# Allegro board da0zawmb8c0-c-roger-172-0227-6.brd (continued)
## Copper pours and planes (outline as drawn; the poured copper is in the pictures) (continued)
VCCDSW_GPIO on TOP (solid shape): 85.28,31.61 85.28,31.23 84.77,31.23 84.52,30.97 84.01,30.97 83.88,31.1 83.88,31.74 84.14,31.99 84.14,32.37 84.52,32.37
VCCDUSB_1P05 on TOP (solid shape): 103.27,37.16 103.71,37.16 104.07,36.79 104.07,36.56 103.62,36.1 102.96,36.1 102.73,36.33 102.73,37.25 102.76,37.28 103.16,37.28
VCCDUSB_1P05 on IN2 (solid shape): outline of 607 points within 89.67,37.71 100.39,41.21
VCCHDA on TOP (solid shape): outline of 728 points within 85.09,32.27 88.73,46.29
VCCMPHYGTAON_1P05 on TOP (solid shape): outline of 1117 points within 88.96,29.93 104.71,44.69
VCCMPHYGTAON_1P05 on BOTTOM (solid shape): 103.8,30.34 104.48,30.34 104.63,30.19 104.63,28.97 104.48,28.82 103.67,28.82 103.64,28.79 103.4,28.68 103.29,28.43 103.23,28.37 102.82,28.37 102.78,28.41 102.78,29.96 103.16,30.34 103.16,30.35 103.32,30.51 103.63,30.51
VCCMPHYGTAON_1P05 on BOTTOM (solid shape): 90.96,44.85 90.96,44.76 90.95,44.75 90.91,44.59 90.98,44.45 90.99,44.43 90.99,44.41 90.99,44.17 90.99,44.15 90.98,44.13 90.91,43.96 90.98,43.8 90.99,43.78 90.99,43.76 90.99,43.52 90.99,43.5 90.98,43.48 90.91,43.36 90.93,43.22 90.94,43.21 90.94,43.11 90.87,43.04 89.47,43.04 89.24,43.26 89.24,44.23 89.31,44.29 89.31,44.93 89.31,44.94 89.59,44.94 89.6,44.94 90.87,44.94
VCCPRIM_1P05 on BOTTOM (solid shape): 99.69,41.09 100.95,41.09 100.95,40.32 101.23,40.04 101.23,39.4 101.8,38.83 101.8,35.76 101.71,35.67 100.8,35.67 100.72,35.75 100.72,36.35 100.74,36.42 100.75,36.49 100.74,36.55 100.72,36.62 100.72,37.55 100.29,37.98 100.29,38.92 99.5,39.71 99.5,40.4 99.17,40.73 99.17,41.01 99.35,41.18 99.59,41.18
VCCPRIM_1P05 on BOTTOM (solid shape): 88.4,44.11 88.41,44.09 88.4,43.92 88.45,43.8 88.45,43.48 88.4,43.38 88.39,43.24 88.38,43.22 88.2,43.04 87.79,43.04 87.77,43.04 87.75,43.05 87.5,43.31 87.22,43.31 87.2,43.33 87.19,43.35 87.01,43.55 86.76,43.46 86.63,43.33 86.62,43.32 86.57,43.32 86.56,43.33 86.36,43.53 86.22,43.53 86.21,43.54 85.93,43.48 85.91,43.19 85.91,43.09 85.82,43.04 85.24,43.04 85.21,43.06 85.2,43.08 85.17,43.16 85.11,43.23 85.08,43.3 85.11,43.37 85.6,43.86 85.8,43.86 86.24,44.31 88.2,44.31
VCCPRIM_1P05 on IN2 (solid shape): outline of 2292 points within 83.86,39.86 100.91,48.25
VCCPRIM_1P8 on BOTTOM (solid shape): 96.96,32.68 96.96,30.95 96.76,30.75 96.76,29.72 96.7,29.62 96.68,29.5 96.71,29.37 96.78,29.26 96.78,28.64 96.77,28.63 96.77,28.28 97.02,28.03 97.02,27.65 96.89,27.52 96.73,27.52 96.68,27.57 96.68,27.87 96.1,28.46 95.95,28.46 95.67,28.74 95.67,32.12 95.67,32.45 95.66,32.46 95.66,32.73 95.75,32.82 95.83,32.81 95.87,32.8 96,32.83 96.11,32.9 96.73,32.9
VCCPRIM_1P8 on BOTTOM (solid shape): outline of 84 points within 85.84,39.79 89.34,41.57
VCCPRIM_1P8 on SVCC (solid shape): 85.33,41.51 85.64,41.33 85.95,41.51 86.28,41.51 86.59,41.33 86.91,41.51 87.15,41.51 87.27,41.42 87.41,41.38 87.51,41.4 87.6,41.44 87.64,41.47 87.82,41.28 87.82,39.87 87.77,39.86 87.49,39.53 87.77,39.21 87.82,39.2 87.82,39.04 87.78,39.04 87.5,38.71 87.78,38.39 87.82,38.38 87.82,38.21 87.84,38.12 87.89,38.03 90.05,35.87 90.13,35.82 90.23,35.8 94.77,35.8 94.84,35.78 94.91,35.77 94.97,35.78 95.04,35.8 95.21,35.8 97.85,33.15 97.85,32.48 97.49,32.12 95.29,32.12 94.98,32.42 94.9,32.48 94.8,32.5 93.92,32.5 93.85,32.52 93.79,32.52 93.73,32.52 93.66,32.5 88.15,32.5 88.02,32.66 87.82,32.73 87.82,32.73 87.82,32.75 87.8,32.85 87.74,32.93 86.55,34.13 86.55,34.91 86.53,35.01 86.47,35.09 84.9,36.67 84.9,37.6 85.02,37.86 84.9,38.11 84.9,38.64 84.97,38.84 84.91,39.05 84.9,39.06 84.9,39.18 84.91,39.19 84.99,39.42 84.9,39.63 84.9,41.16 85.26,41.51
VCCPRIM_3P3 on BOTTOM (solid shape): 87.44,33.01 87.44,30.54 87.29,30.39 87.29,30.08 87.23,30.03 87.23,28.84 87.29,28.79 87.29,28.76 87.29,28.48 87.4,28.37 87.4,27.38 87.18,27.16 85.91,27.16 85.84,27.24 85.84,28.19 86.22,28.57 86.22,28.61 86.24,28.64 86.24,29.3 86.22,29.33 86.22,29.53 86.29,29.75 86.22,29.98 86.22,31.99 85.94,32.27 85.83,32.37 85.83,33.21 86,33.39 87.06,33.39
VCCPRIM_3P3 on BOTTOM (solid shape): outline of 81 points within 83.45,40.47 84.67,47.48
VCCPRIM_3P3 on IN2 (solid shape): 84.44,41.55 84.44,40.55 84.26,40.37 83.2,40.37 83.04,40.52 83.04,41.9 83.12,41.97 84.02,41.97
VCCPRIM_3P3 on SVCC (solid shape): 84.39,41.66 84.39,39.6 84.33,39.41 84.39,39.22 84.39,39.06 84.31,38.85 84.39,38.64 84.39,37.99 84.37,37.92 84.36,37.86 84.37,37.79 84.39,37.72 84.39,36.56 84.41,36.46 84.46,36.38 86.04,34.81 86.04,34.02 86.06,33.92 86.12,33.84 87.31,32.65 87.31,32.35 86.82,31.86 80.18,31.86 79.95,32.1 79.95,32.21 79.96,32.28 79.97,32.35 79.96,32.41 79.95,32.48 79.95,32.77 80.26,33.09 80.3,33.11 80.33,33.13 83.12,33.13 83.22,33.15 83.3,33.21 83.55,33.46 83.61,33.54 83.63,33.64 83.63,35.29 83.61,35.39 83.55,35.47 82.74,36.29 82.74,36.72 83.07,37.07 82.74,37.43 82.74,38.34 82.92,38.46 82.99,38.66 82.95,38.83 82.83,38.95 82.95,39.07 82.99,39.23 82.92,39.44 82.74,39.55 82.74,40.77 83.86,41.9 84.16,41.9
VCCPRIM_3P33 on TOP (solid shape): 99.34,36.77 99.4,36.77 99.46,36.75 99.52,36.74 99.76,36.5 99.76,35.7 99.86,35.6 99.86,34.91 99.87,34.9 99.76,34.79 99.55,34.79 99.54,34.8 99.39,34.8 99.27,34.91 99.27,35.39 98.97,35.7 98.97,36.05 98.76,36.27 98.76,37.02 98.84,37.11 99.01,37.11
VCCPRIM_3P33 on IN2 (solid shape): outline of 784 points within 86.93,35.1 99.6,42.02
VCCSPI on TOP (solid shape): outline of 290 points within 83.15,36.94 85.27,44.56
3602_VIN on BOTTOM (solid shape): 136.56,51.19 134.78,51.19 134.53,50.94 134.28,50.94 134.17,51.04 134.17,51.34 134.48,51.65 136.56,51.65
5213LX_1.8V on TOP (solid shape): 40.02,32.02 40.02,31.63 39.84,31.46 39.74,31.46 39.56,31.28 39.56,30.69 39.48,30.62 39.48,30.29 39.51,30.26 39.51,30.1 39.54,30.02 39.6,29.98 39.62,29.97 39.64,29.94 39.64,29.9 40.49,29.9 40.53,29.85 40.53,29.63 40.51,29.6 39.64,29.6 39.62,29.58 39.43,29.58 39.18,29.32 39.18,28.82 38.67,28.31 38.03,28.31 37.91,28.43 37.91,31.86 38.16,32.12 39.91,32.12
8813BOOT1 on TOP (solid shape): 77.94,114.54 77.97,114.53 77.99,114.49 77.99,113.96 77.97,113.92 77.94,113.91 77.48,113.91 75.91,112.33 75.2,112.33 75.09,112.43 75.09,113.12 75.14,113.17 75.83,113.17 77.2,114.54
8813BOOT2 on TOP (solid shape): 76.97,108.32 78.29,108.32 78.42,108.19 78.42,107.56 78.29,107.43 78.22,107.43 77.63,107.43 77.59,107.43 76.52,107.43 75.55,108.39 75.09,108.39 75.08,108.41 75.08,109.09 75.21,109.22 76.07,109.22
8813LGAT1 on TOP (solid shape): 77.94,112.03 77.94,111.62 77.71,111.39 75.6,111.39 75.57,111.41 75.55,111.44 75.55,111.63 75.57,111.67 75.6,111.68 76.37,111.68 76.37,111.7 76.44,111.7 77.05,112.3 77.66,112.3
8813LGAT1 on BOTTOM (solid shape): 77.33,117.33 77.33,116.7 77.31,116.66 77.28,116.65 76.8,116.65 76.41,116.27 76.41,116.14 76.24,115.96 75.35,115.96 75.3,115.91 75.3,115.61 75.25,115.56 74.84,115.56 74.76,115.63 74.76,116.19 75.04,116.47 75.04,117.56 75.14,117.66 77,117.66
8813LGAT2 on BOTTOM (solid shape): 84.06,110.02 84.06,107.83 83.98,107.76 83.32,107.76 83.22,107.86 83.22,110.1 83.42,110.3 83.78,110.3
8813PHASE1 on TOP (solid shape): 77.96,113.22 78,113.2 78.01,113.17 78.01,112.56 77.99,112.53 77.02,112.53 76.39,111.9 75.6,111.9 75.57,111.91 75.55,111.95 75.55,112.08 75.65,112.18 75.93,112.18 75.96,112.2 76.98,113.22
8813PHASE1 on BOTTOM (solid shape): 78.75,122.01 78.87,121.93 79.01,121.91 79.07,121.91 79.14,121.93 79.17,121.92 79.36,121.73 79.38,121.71 79.38,121.68 79.37,121.63 79.4,121.5 79.46,121.38 79.49,121.31 79.46,121.25 79.39,121.13 79.36,120.99 79.4,120.83 79.51,120.68 79.51,120.66 79.51,117.66 79.51,117.64 79.5,117.62 79.28,117.41 77.76,117.41 77.1,118.07 76.29,118.07 75.96,118.4 75.96,121.25 76.72,122.01
8813PHASE2 on TOP (solid shape): 76.46,109.66 76.72,109.66 76.92,109.46 77.36,109.46 78.29,109.46 78.42,109.33 78.42,108.83 78.29,108.7 76.8,108.7 76.11,109.38 75.65,109.38 75.55,109.49 75.55,109.59 75.63,109.66 76.46,109.66
8813PHASE2 on BOTTOM (solid shape): 82.62,114.81 82.62,110.82 82.84,110.6 82.84,108.98 82.71,108.85 79.56,108.85 79.39,109.03 79.39,114.67 79.82,115.1 82.33,115.1
8813UGATE1 on BOTTOM (solid shape): 73.67,116.04 73.67,115.63 73.94,115.37 74.65,115.37 75.2,114.82 75.2,114.21 75.09,114.11 73.98,114.11 73.68,114.4 72.82,114.4 72.68,114.54 72.68,116.06 72.78,116.17 73.54,116.17
8813UGATE1_1 on BOTTOM (solid shape): 71.31,117.59 71.31,116.85 71.41,116.75 71.41,116.55 71.51,116.45 71.55,116.4 71.59,116.37 71.66,116.29 71.84,116.29 72.07,116.29 72.2,116.17 72.2,115.33 72.1,115.23 71.33,115.23 71.13,115.43 71.13,115.58 70.98,115.73 70.94,115.78 70.9,115.81 70.7,116.01 70.7,116.32 70.57,116.45 70.12,116.45 69.99,116.57 69.99,116.93 70.09,117.03 70.42,117.03 70.7,117.31 70.7,117.59 70.72,117.61 71.28,117.61
8813UGATE2 on TOP (solid shape): 74.81,109.23 74.85,109.22 74.86,109.18 74.86,108.34 74.97,108.24 75.37,108.24 77.07,106.54 77.91,106.54 78.04,106.41 78.04,105.52 77.91,105.4 77.02,105.4 75.12,107.3 75.12,107.68 74.56,108.24 74.56,108.39 74.57,108.39 74.57,109.18 74.59,109.22 74.62,109.23
8813UGATE2_1 on BOTTOM (solid shape): 84.75,104.53 84.75,103.87 84.21,103.34 84.17,103.34 84.17,103.34 83.37,103.34 83.34,103.35 83.32,103.39 83.32,103.97 83.37,104.02 83.86,104.02 84.01,104.02 84.01,104.17 84.14,104.3 84.14,104.58 84.15,104.62 84.19,104.63 84.64,104.63
24780_BST on BOTTOM (solid shape): 130.79,30.19 130.79,30.18 130.84,30.13 130.84,30.12 130.99,29.97 131.71,29.97 131.74,30 132.57,30 132.61,29.98 132.62,29.95 132.62,29.82 132.61,29.81 131.76,29.81 131.7,29.75 131.52,29.75 131.51,29.73 131.38,29.74 131.14,29.74 130.8,29.4 130.15,29.4 130.12,29.41 130.1,29.45 130.1,30.17 130.12,30.2 130.15,30.22 130.76,30.22
24780_LX on BOTTOM (solid shape): 125.61,31.63 125.61,31.21 125.35,30.95 125.35,27.44 125.21,27.3 124,27.3 123.66,26.96 123.66,26.05 123.43,25.81 122.77,25.81 122.54,26.05 122.54,26.86 122.11,27.29 119.07,27.29 118.51,27.85 118.51,30.27 119.23,30.99 123.66,30.99 123.77,31.1 123.77,31.69 123.86,31.78 125.46,31.78
24780_LX on BOTTOM (solid shape): 131.14,31.67 131.17,31.66 131.19,31.64 131.27,31.53 131.39,31.46 131.4,31.45 131.69,31.16 131.69,30.88 131.76,30.81 131.82,30.81 131.82,30.81 132.57,30.81 132.61,30.79 132.62,30.76 132.62,30.62 132.62,30.61 131.6,30.61 131.6,30.62 131.4,30.81 130.11,30.81 130.07,30.83 130.06,30.86 130.06,31.62 130.07,31.66 130.11,31.67
24780_VCC on BOTTOM (solid shape): 130.95,33.33 130.95,32.95 131.13,32.77 132.62,31.28 132.62,31.06 132.6,31.02 132.57,31.01 131.87,31.01 131.84,31.02 131.82,31.06 131.82,31.21 130.39,32.65 130.35,32.65 130.32,32.66 130.3,32.7 130.3,33.07 130.27,33.1 130.27,33.4 130.32,33.45 130.83,33.45
+1.03_GFX on BOTTOM (solid shape): 119.19,123.18 119.19,122.13 118.93,121.88 118.93,119.11 118.81,118.99 118.47,118.99 118.46,118.99 117.91,118.99 117.26,119.65 117.26,121.86 117.66,122.26 117.66,122.92 118.04,123.3 119.06,123.3
+1.03_GFX on BOTTOM (solid shape): 71.56,105.52 72.58,105.52 72.76,105.35 72.76,102.93 72.88,102.81 72.88,102.02 72.58,102.02 72.25,101.69 72.25,101.18 72.15,101.08 71.05,101.08 70.93,101.2 70.93,105.12 70.93,105.52 71.05,105.65 71.44,105.65
+1.03_GFX on IN1 (solid shape): outline of 470 points within 66.15,104.43 72.96,118.22
+1.03_GFX on IN1 (solid shape): outline of 602 points within 94.42,121.4 118.93,125.97
+1.03_GFX on IN2 (solid shape): outline of 619 points within 109.41,108.57 118.81,123.68
+601_VCC on TOP (solid shape): 216.09,16.75 216.09,16.62 215.96,16.5 214.06,16.5 213.98,16.57 213.95,16.65 213.98,16.72 214.08,16.85 214.11,17 214,17.27 213.73,17.39 213.57,17.35 213.44,17.26 213.37,17.23 213.29,17.26 212.41,17.26 212.28,17.39 212.28,17.88 212.4,18.06 212.44,18.27 212.44,18.41 212.46,18.43 214.41,18.43
+601_VCC on TOP (solid shape): 204.91,19.04 204.91,18.4 204.38,17.87 204.38,12.71 204.62,12.47 205.32,11.77 205.85,11.77 205.98,11.64 206.46,11.64 206.54,11.61 206.64,11.59 206.74,11.59 206.76,11.61 206.89,11.7 206.97,11.83 207.38,12.23 207.38,12.69 207.58,12.89 207.58,14.51 208.55,15.48 209.36,15.48 209.48,15.35 209.48,14.86 209.37,14.68 209.32,14.47 209.32,14.38 208.47,13.52 208.47,12.5 208.46,12.5 208.46,11.92 207.88,11.34 207.88,10.6 207.83,10.55 206.03,10.55 205.6,10.98 205.6,11.03 205.31,11.32 204.76,11.32 204.64,11.44 204.63,11.44 204.58,11.49 204.58,11.73 203.54,12.77 203.54,17.51 203.54,18.3 204.4,19.16 204.79,19.16
+601_VCC on IN2 (solid shape): outline of 165 points within 207.07,11.5 215.83,18.02
+AZA_VDD on BOTTOM (solid shape): 211.26,26.83 211.26,26.12 210.96,25.82 210.96,25.06 210.22,25.06 210.12,25.16 210.12,26.76 210.2,26.83 210.2,27.34 210.22,27.37 210.73,27.37
+FB_PLLAVDD on IN2 (solid shape): outline of 95 points within 106.51,97.4 112.39,98.96
+G_SEN_PW on TOP (solid shape): 58.11,17.64 58.11,17.11 57.99,16.98 56.91,16.98 56.75,17.13 56.75,17.59 56.91,17.74 58.01,17.74
+SMDDR_VREF_DIMM on TOP (solid shape): 49.85,53.71 49.85,53.2 50.23,52.82 50.23,49.9 50.48,49.64 50.48,48.75 50.35,48.63 49.59,48.63 48.96,49.26 48.96,52.06 48.7,52.32 48.7,53.23 48.91,53.45 49.08,53.45 49.46,53.83 49.72,53.83
+TYPEC_VBUS on TOP (solid shape): 14.67,10.65 14.67,10.27 15.05,9.89 15.66,9.89 15.75,9.79 15.75,8.64 15.54,8.43 14.79,8.43 13.66,9.56 12.73,9.56 12.63,9.66 12.63,10.65 12.71,10.73 14.59,10.73
+TYPEC_VBUS on TOP (solid shape): 16.81,15.46 16.81,13.89 16.72,13.8 16.22,13.8 16.06,13.96 15.3,13.96 15.29,13.94 15.07,13.94 14.79,13.67 14.79,13.19 14.24,12.64 13.83,12.64 13.4,13.07 13.02,13.07 12.76,13.32 12.76,13.45 12.78,13.48 12.79,13.48 12.96,13.62 13.02,13.83 12.99,13.96 12.92,14.08 12.91,14.11 12.93,14.15 13.03,14.29 13.07,14.47 13.07,14.63 13.31,14.87 13.52,14.87 13.58,14.85 13.65,14.84 13.92,14.96 14.03,15.23 14.02,15.33 13.97,15.43 13.97,15.53 14.06,15.58 16.69,15.58
+TYPEC_VBUS on BOTTOM (solid shape): 6.72,14.79 7.45,14.79 7.5,14.74 7.5,14.57 7.45,14.51 6.87,14.51 6.59,14.24 5.9,14.24 5.83,14.31 5.83,14.74 5.93,14.85 6.67,14.85
+TYPEC_VBUS on BOTTOM (solid shape): 6.82,17.28 7.4,17.28 7.48,17.21 7.48,17.08 7.4,17 6.41,17 6.28,16.88 5.9,16.88 5.78,17 5.78,17.54 5.88,17.64 6.46,17.64
+TYPEC_VBUS on BOTTOM (solid shape): 16.11,16.78 16.11,14.01 15.05,12.94 13.83,12.94 13.42,12.53 13.04,12.53 12.89,12.69 12.89,13.19 12.89,13.19 12.89,13.55 12.98,13.67 13.02,13.83 12.99,13.96 12.92,14.08 12.9,14.15 12.92,14.21 13,14.34 13.02,14.49 13.02,14.59 13.19,14.77 13.85,14.77 14.13,15.05 14.13,16.65 14.29,16.81 16.08,16.81
+TYPEC_VBUS on IN2 (solid shape): outline of 1338 points within 5.65,7.55 16.7,19.46
+TYPEC_VBUS_C on TOP (solid shape): 19.75,16.75 19.75,13.19 19.42,12.87 17.35,12.87 17.1,13.13 17.1,16.84 17.36,17.11 19.39,17.11
+TYPEC_VBUS_C on BOTTOM (solid shape): 19.61,16.93 21.59,16.93 21.6,16.9 21.63,16.85 21.67,16.81 21.71,16.77 21.75,16.73 21.81,16.71 21.86,16.69 21.92,16.68 21.98,16.68 22.03,16.69 22.09,16.71 22.14,16.73 22.19,16.77 22.23,16.81 22.26,16.85 22.29,16.9 22.3,16.93 22.54,16.93 22.99,16.48 22.99,16.46 23.65,16.46 23.75,16.35 23.75,15.89 23.63,15.76 22.99,15.76 22.99,15.71 22.55,15.71 22.33,15.49 22.3,15.48 22.26,15.45 22.22,15.41 22.18,15.37 22.15,15.33 22.13,15.28 22.12,15.23 22.11,15.17 22.11,15.12 22.11,15.07 22.13,15.02 22.15,14.97 22.18,14.93 22.2,14.89 22.21,14.87 22.21,14.84 22.21,14.81 22.2,14.78 22.17,14.75 22.14,14.71 22.11,14.67 22.1,14.63 22.07,14.61 20.27,14.61 19.37,13.7 16.95,13.7 16.43,14.22 16.43,15.96 23.61,15.96 23.61,16.26 22.99,16.26 22.99,15.96 16.43,15.96 16.43,16.42 16.44,16.42 16.44,16.88 16.8,17.24 19.29,17.24
+USBPWR0 on TOP (solid shape): 19.49,52.31 19.49,51.02 19.45,50.97 19.45,50.05 19.49,50 19.49,49.77 18.22,49.77 18.1,49.9 17.59,49.9 17.16,50.33 17.16,51.93 17.66,52.44 19.37,52.44
+USBPWR0 on BOTTOM (solid shape): outline of 517 points within 13.9,49.14 23.05,58.79
+USBPWR1 on BOTTOM (solid shape): outline of 146 points within 13.9,37.2 22.54,48.88
+VGPU_CORE on TOP (solid shape): 86.17,122.16 86.17,119.54 86.9,118.81 86.9,118.43 86.17,117.69 86.17,117.23 85.83,116.89 81.36,116.89 80.99,117.26 80.99,119.27 81.85,120.13 81.85,122.67 82.23,123.05 85.28,123.05
+VGPU_CORE on TOP (solid shape): 104.54,102 104.8,101.74 104.81,101.73 104.89,101.63 105.02,101.59 105.12,101.59 105.2,101.56 105.22,101.48 105.22,101.43 105.29,101.22 105.48,101.09 105.49,101.09 105.62,100.95 105.62,100.87 105.61,100.84 105.57,100.82 105.51,100.76 105.51,100.65 105.4,100.55 104.92,100.55 104.12,101.34 104.11,101.38 104.12,101.41 104.32,101.61 104.32,101.61 104.42,101.7 104.45,101.82 104.45,101.96 104.47,101.99 104.5,102.01
+VGPU_CORE on TOP (solid shape): outline of 2023 points within 97.5,100.82 116.77,125.18
+VGPU_CORE on BOTTOM (solid shape): outline of 94 points within 103.95,114.79 116.39,125.84
+VGPU_CORE on BOTTOM (solid shape): outline of 133 points within 80.96,106.54 89.72,122.67
+VGPU_CORE on IN2 (solid shape): outline of 5526 points within 80.61,98.79 113.09,123.61
+VGPU_CORE on SVCC (solid shape): 114.49,125.86 114.49,119.09 109.74,114.34 109.68,114.26 109.66,114.16 109.66,97.5 109.43,97.27 101.77,97.27 101.64,97.4 101.65,97.44 101.65,97.48 101.56,97.72 101.32,97.81 101.28,97.81 101.24,97.8 98.29,100.74 98.3,100.78 98.3,100.83 98.21,101.06 97.97,101.16 97.93,101.16 97.89,101.15 89.27,109.77 89.19,109.82 89.09,109.84 85.64,109.84 78.95,116.53 78.95,124.09 79.24,124.38 85.2,124.38 86.63,124.97 87.22,126.4 87.22,126.48 113.88,126.48
+VGPU_CORE on IN3 (solid shape): outline of 3278 points within 99.05,100.7 113.8,123.25
ADOGND on SGND (solid shape): outline of 98 points within 197.8,29.45 216.72,49.9
ADOGND on SVCC (solid shape): outline of 98 points within 197.8,29.45 216.72,49.9
ADOGND on SGND1 (solid shape): outline of 99 points within 197.8,29.45 216.72,49.9
BAT-V on BOTTOM (solid shape): outline of 509 points within 94.3,14.54 113.32,33.74
ECAGND on TOP (solid shape): 203.03,15.91 203.03,15.48 202.88,15.33 202.88,14.21 202.75,14.08 201.99,14.08 201.86,14.21 201.86,14.82 201.59,15.1 201.59,15.38 201.61,15.4 202.45,15.4 202.53,15.48 202.53,15.84 202.68,15.99 202.96,15.99
ECAGND on TOP (solid shape): 201.99,21.37 201.99,20.91 201.99,20.89 201.84,20.75 201.79,20.58 201.79,20.56 201.76,20.53 201.66,20.54 201.61,20.54 201.56,20.54 201.46,20.53 201.3,20.46 201.23,20.3 201.23,20.02 201.26,19.91 201.34,19.83 201.35,19.82 201.36,19.8 201.36,19.79 201.34,19.75 201.31,19.74 201.28,19.74 201.18,19.65 200.59,19.65 200.39,19.85 200.21,19.85 200.18,19.86 200.16,19.9 200.16,20.79 200.77,21.4 201.23,21.4 201.29,21.45 201.92,21.45
ECAGND on IN1 (solid shape): outline of 140 points within 199.66,14.31 202.63,21.44
FBA_VREFC_1 on BOTTOM (solid shape): 133.86,97.45 133.86,97.04 133.92,96.98 133.92,96.17 133.74,95.99 133.74,94.55 133.54,94.35 133.54,93.71 133.28,93.71 133.28,94.73 133.16,94.86 133.16,96.13 133.28,96.25 133.28,96.78 133.48,96.97 133.48,97.47 133.54,97.5 133.81,97.5
G5335-AGND-1 on IN3 (solid shape): outline of 250 points within 120.84,38.47 124.14,42.79
G5335-AGND-2 on TOP (solid shape): outline of 82 points within 139.51,63.13 142.53,69.07
G5335-LX-1 on BOTTOM (solid shape): 114.74,40.47 116.67,40.47 116.67,39.69 116.67,39.69 116.67,39.46 116.75,39.38 117.38,39.38 117.38,36.82 117.36,36.79 117.18,36.79 117.16,36.77 117.16,35.7 116.98,35.52 116.57,35.52 116.42,35.67 116.42,35.69 116.91,35.69 116.91,36.48 116.67,36.48 116.67,35.69 116.42,35.69 116.42,35.75 116.42,36.46 116.45,36.49 116.47,36.49 116.47,38.72 114.08,38.72 114.08,36.67 114.06,36.65 114.03,36.6 114,36.54 113.99,36.48 113.98,36.42 113.98,36.36 113.99,36.3 114.01,36.24 114.03,36.19 114.06,36.15 114.08,36.12 114.08,35.86 114.07,35.82 114.06,35.76 114.06,35.69 114.07,35.64 114.08,35.58 114.11,35.53 114.14,35.48 114.18,35.44 114.23,35.41 114.28,35.38 114.31,35.36 114.41,35.27 115.1,35.27 115.28,35.09 115.28,34.39 115.17,34.29 113.05,34.29 112.72,34.63 112.72,36.25 112.71,36.26 112.71,36.29 111.69,37.3 111.69,38.96 116.19,38.96 116.19,39.21 115.4,39.21 115.4,38.96 111.69,38.96 111.69,39.94 111.52,40.12 111.52,40.6 111.64,40.73 114.49,40.73
G5335-LX-2 on BOTTOM (solid shape): 137.88,71.11 137.88,70.09 137.73,69.94 136.89,69.94 136.69,69.73 136.69,69.65 136.68,69.62 136.68,69.57 136.67,69.52 136.68,69.47 136.69,69.44 136.69,69.08 136.68,69.08 136.68,68.29 136.69,68.29 136.69,68.06 136.79,67.96 137.35,67.96 137.38,67.95 137.39,67.93 137.4,67.91 137.4,65.39 137.17,65.16 137.17,64.38 137.16,64.35 137.15,64.33 136.95,64.33 136.94,64.35 136.93,64.38 136.93,65.08 136.68,65.08 136.68,64.38 136.67,64.35 136.66,64.33 136.46,64.33 136.44,64.35 136.43,64.38 136.43,65.31 136.51,65.39 136.51,67.19 136.41,67.3 136.2,67.3 136.2,67.31 135.38,67.31 135.13,67.56 136.2,67.56 136.2,67.81 135.41,67.81 135.41,67.56 135.13,67.56 134.86,67.83 134.86,68.06 134.78,68.13 134.73,68.13 134.02,68.13 133.95,68.13 133.62,68.46 133.62,69.48 133.13,69.96 133.13,70.11 133.26,70.24 133.26,72 133.49,72.22 136.76,72.22
G5335-VCC-1 on BOTTOM (solid shape): 118.71,41.85 118.71,40.83 118.53,40.65 118.35,40.65 118.18,40.48 118.17,40.48 118.17,40.16 118.16,40.12 118.16,40.09 118.16,39.74 118.14,39.7 118.11,39.69 117.97,39.69 117.93,39.7 117.92,39.74 117.92,41.21 117.8,41.32 117.6,41.32 117.54,41.39 117.54,42.05 117.55,42.08 117.59,42.1 118.45,42.1
G5719LX1.5V on BOTTOM (solid shape): 165.62,24.04 165.7,24.01 165.72,23.93 165.72,23.89 165.77,23.71 165.92,23.56 165.92,23.53 165.92,21.96 165.87,21.9 165.85,21.9 165.67,21.8 165.57,21.62 165.57,21.6 165.42,21.45 164.53,21.45 164.34,21.63 164.31,21.69 164.27,21.74 164.27,21.96 164.15,22.08 163,22.08 162.88,22.21 162.88,22.77 162.89,22.81 162.97,22.82 164.06,22.82 164.1,22.82 164.14,22.85 164.27,22.85 164.4,22.97 164.4,23.35 164.58,23.53 164.58,23.85 164.77,24.04
ISEN1N_SA on TOP (solid shape): 142.94,56.12 142.94,55.61 143.19,55.36 143.19,54.72 142.99,54.52 142.99,54.24 142.84,54.09 141.92,54.09 141.79,54.22 141.79,54.6 142.05,54.85 142.05,56.25 142.17,56.37 142.68,56.37
L_SPK+ on TOP (solid shape): 115.16,17.64 115.16,16.47 115.4,16.23 115.4,13.58 115.35,13.52 114.13,13.52 113.92,13.74 113.92,17.61 114.04,17.74 115.06,17.74
L_SPK+ on BOTTOM (solid shape): 210,33.07 210,32.8 209.88,32.68 208.99,32.68 208.95,32.72 207.26,32.72 207.26,32.73 207.26,32.91 207.27,32.93 208.74,32.93 209,33.18 209.89,33.18
L_SPK+ on IN2 (solid shape): 115.44,14.78 115.44,13.66 115.31,13.54 114.27,13.54 114.1,13.71 114.1,14.58 114.36,14.85 115.38,14.85
L_SPK+ on IN2 (solid shape): 210,33.32 210,32.84 209.87,32.71 208.38,32.71 208.27,32.6 208.27,32.04 208.42,31.89 208.42,30.01 208.32,29.91 207.38,29.91 207.17,30.11 207.17,33.08 207.35,33.26 208.65,33.26 208.84,33.45 209.87,33.45
L_SPK+_1 on TOP (solid shape): 116.09,21.25 116.09,20.13 115.1,19.14 115.1,18.32 115,18.22 114.21,18.22 114.08,18.35 114.08,19.47 114.46,19.85 114.46,19.87 114.5,19.88 114.71,20 114.79,20.23 114.73,20.43 114.57,20.56 114.54,20.57 114.54,20.89 114.97,21.32 115.88,21.32 115.89,21.32 116.01,21.32
L_SPK+_1 on BOTTOM (solid shape): 116.57,22.16 116.57,20.84 116.09,20.36 116.09,19.49 115.89,19.29 114.92,19.29 114.82,19.39 114.82,20.27 114.83,20.32 115.5,20.99 115.5,22.08 115.63,22.21 116.52,22.21
L_SPK- on TOP (solid shape): 116.76,17.65 116.76,14.68 116.93,14.51 116.93,13.65 116.8,13.52 115.94,13.52 115.73,13.73 115.73,16.46 115.47,16.72 115.47,17.7 115.52,17.75 116.66,17.75
L_SPK- on BOTTOM (solid shape): 208.95,32.58 209.17,32.58 209.61,32.58 209.7,32.49 209.7,32.21 209.56,32.07 208.72,32.07 208.47,32.32 207.27,32.32 207.26,32.33 207.26,32.5 207.29,32.53 208.25,32.53 208.57,32.53 208.64,32.59 208.94,32.59
L_SPK- on IN2 (solid shape): 209.06,32.58 209.1,32.57 209.15,32.58 209.2,32.59 209.58,32.59 209.66,32.56 209.74,32.55 209.82,32.56 209.9,32.59 211.22,32.59 211.26,32.55 211.26,31.33 211.06,31.13 210.4,31.13 210.12,31.41 210.12,31.81 209.86,32.07 208.67,32.07 208.57,32.17 208.57,32.47 208.68,32.59 209.01,32.59
L_SPK-_1 on TOP (solid shape): 117.29,21.2 117.29,19.79 116.6,19.1 116.6,18.27 116.47,18.15 115.48,18.15 115.4,18.22 115.4,19.01 116.39,20 116.39,21.04 116.67,21.32 117.16,21.32
L_SPK-_1 on BOTTOM (solid shape): 117.64,19.37 117.51,19.24 116.65,19.24 116.5,19.39 116.5,20.31 116.9,20.71 116.9,22.24 117,22.34 117.64,22.34
MIC2-VREFO on TOP (solid shape): 213.45,44.11 213.45,42.73 213.37,42.66 212.74,42.66 212.38,43.01 212.38,43.65 212.41,43.67 212.46,43.67 212.74,43.95 212.79,43.95 212.99,44.16 213.4,44.16
PBA_PWR on TOP (solid shape): 49.26,21.68 49.26,21.22 49.59,20.89 49.59,20.64 49.53,20.46 49.58,20.27 49.59,20.26 49.59,20.1 49.55,20.09 49.26,19.74 49.55,19.39 49.59,19.38 49.59,19.15 49.43,18.99 49.42,18.98 49.23,18.85 49.16,18.63 49.13,18.56 49.06,18.53 47.43,18.53 47.31,18.66 47.31,20.43 47.86,20.99 47.86,21.53 48.19,21.86 49.08,21.86
PBA_PWR_C on BOTTOM (solid shape): 56.45,21.7 56.96,21.7 57.08,21.58 57.08,19.93 56.96,19.8 55.81,19.8 55.56,20.05 55.56,22.08 55.69,22.21 55.94,22.21
PBA_PWR_R on TOP (solid shape): 50.66,18.6 50.66,16.8 50.35,16.5 50.1,16.5 50.07,16.52 49.41,16.52 49.16,16.78 47.53,16.78 47.31,17 47.31,18.02 47.56,18.27 49.46,18.27 49.48,18.29 49.5,18.28 49.6,18.29 49.69,18.33 49.7,18.34 49.72,18.34 49.92,18.54 49.92,18.62 50.09,18.78 50.48,18.78
PBA_PWR_R on BOTTOM (solid shape): 55.12,22.02 55.12,20.23 55.07,20.14 54.97,20.14 54.89,20.17 54.8,20.18 54.63,20.14 54.5,20.03 54.45,20 54.39,20 54.25,20.13 54.06,20.18 54.04,20.18 53.77,20.07 53.66,19.8 53.67,19.68 53.73,19.58 53.73,19.47 53.64,19.42 53.35,19.42 53.05,19.72 53.05,20.2 53.35,20.51 54.11,20.51 54.39,20.79 54.39,21.96 54.52,22.08 55.05,22.08
PHASE1_CORE on BOTTOM (solid shape): 129.68,66.31 129.68,65.21 130.54,64.35 130.54,63.82 130.78,63.57 132.79,63.57 132.9,63.46 132.9,62.72 132.57,62.39 130.87,62.39 130.31,61.84 130.31,60.23 130.29,60.21 127.01,60.21 126.77,60.45 126.77,61.44 127.11,61.78 128.54,61.78 128.64,61.89 128.64,62.39 128.56,62.47 127.06,62.47 126.1,63.44 126.1,66.2 126.45,66.56 129.42,66.56
PHASE2_CORE on BOTTOM (solid shape): 131.33,55.82 131.33,55.1 131.51,54.93 131.74,54.93 131.77,54.91 131.79,54.88 131.79,54.27 131.53,54.01 130.69,54.01 130.47,53.78 130.47,52.69 129.53,51.75 128.56,51.75 128.2,51.4 128.2,50.68 128.13,50.61 124.95,50.61 124.81,50.75 124.81,52.07 127.37,54.62 128.46,54.62 128.61,54.77 128.61,55.15 128.46,55.31 127.39,55.31 127.19,55.51 127.19,56.12 127.85,56.78 130.36,56.78
PHASE_GT on BOTTOM (solid shape): outline of 92 points within 113.55,76.06 120.48,81.39
PHASE_SA on BOTTOM (solid shape): 136.26,43.78 136.26,42.99 137.02,42.23 137.02,39.79 136.82,39.58 136.82,38.24 136.74,38.16 135.14,38.16 135.11,38.14 134.98,38.14 133.36,36.52 133.36,36.38 132.98,36 132.24,36 131.71,36.54 131.71,38.5 131.73,38.54 131.76,38.56 132.03,38.56 132.12,38.59 132.16,38.68 132.16,39.06 132.12,39.15 132.03,39.19 131.76,39.19 131.73,39.21 131.71,39.24 131.71,40.5 131.89,40.68 133.8,40.68 134.45,41.33 134.45,43.24 135.27,44.06 135.98,44.06
R_SPK+ on TOP (solid shape): 185.15,15.61 185.15,15.48 185,15.33 184.67,15.33 184.41,15.07 184.41,14.39 184.17,14.15 183.41,14.15 183.4,14.16 183.4,15.12 183.68,15.4 184.11,15.4 184.52,15.81 184.95,15.81
R_SPK+ on TOP (solid shape): 119.14,17.72 119.17,17.7 119.19,17.66 119.19,16.85 119.31,16.55 119.62,16.42 119.67,16.42 119.71,16.43 119.8,16.41 119.84,16.33 119.84,15.43 119.82,15.39 119.78,15.38 118.98,15.38 118.49,15.87 118.49,17.54 118.67,17.72
R_SPK+ on BOTTOM (solid shape): 208.84,31.33 209,31.33 209.04,31.33 209.98,31.33 210.12,31.19 210.12,30.96 209.98,30.82 209.06,30.82 208.36,31.52 207.28,31.52 207.26,31.54 207.26,31.7 207.29,31.73 208.25,31.73 208.44,31.73
R_SPK+ on IN3 (solid shape): 185.53,15.33 185.91,15.33 185.91,14.39 185.66,14.13 184.29,14.13 183.7,14.72 183.7,15.68 183.96,15.94 184.92,15.94
R_SPK+ on IN3 (solid shape): outline of 162 points within 204.74,18.02 210.13,31.31
R_SPK+_1 on TOP (solid shape): 119.44,21.12 119.44,19.57 119.19,19.32 119.19,19.14 119.19,18.22 119.17,18.19 119.14,18.17 118.48,18.17 118.38,18.27 118.38,18.91 118.73,19.26 118.78,19.31 118.78,20.66 118.73,20.71 118.73,21.25 118.81,21.32 119.24,21.32
R_SPK+_1 on BOTTOM (solid shape): 119.66,22.17 119.66,19.73 119.31,19.38 118.93,19.38 118.86,19.45 118.86,20.3 118.97,20.4 118.97,22.24 119.03,22.3 119.54,22.3
R_SPK- on TOP (solid shape): 185.48,12.53 186.47,12.53 186.55,12.46 186.55,11.54 186.45,11.44 185.02,11.44 184.72,11.75 184.72,12.25 185.02,12.56 185.46,12.56
R_SPK- on TOP (solid shape): 118.13,17.73 118.17,17.71 118.18,17.68 118.18,15.07 118.26,15.07 118.3,15.06 118.31,15.02 118.31,14.34 117.77,14.34 117.07,15.04 117.07,17.63 117.17,17.73
R_SPK- on BOTTOM (solid shape): 208.69,31.94 209.86,31.94 209.95,31.85 209.95,31.57 209.81,31.43 209.26,31.43 208.91,31.43 208.42,31.92 207.26,31.92 207.26,32.11 207.28,32.13 208.25,32.13 208.5,32.13
R_SPK- on IN3 (solid shape): 187.46,14.36 187.46,13.73 186.47,12.74 186.47,12.15 186.42,12.1 185.87,12.1 185.63,12.33 185.63,12.51 185.43,12.71 185.43,13.09 186.96,14.62 187.21,14.62
R_SPK- on IN3 (solid shape): outline of 253 points within 206.28,16.32 211.44,32.55
R_SPK-_1 on TOP (solid shape): 117.93,21.31 118.29,21.31 118.4,21.2 118.4,20.61 118.47,20.54 118.47,19.44 118.07,19.04 118.07,18.21 118.06,18.17 118.02,18.16 116.97,18.16 116.9,18.22 116.9,18.97 117.21,19.28 117.22,19.28 117.38,19.38 117.47,19.53 117.47,19.54 117.59,19.67 117.59,21.14 117.78,21.32 117.92,21.32
R_SPK-_1 on BOTTOM (solid shape): 118.65,22.21 118.65,20.52 118.56,20.42 118.56,19.5 118.48,19.42 118.02,19.42 117.96,19.48 117.96,22.27 118.02,22.34 118.53,22.34
RING2 on TOP (solid shape): 214.71,44.89 214.77,44.86 214.85,44.85 215.13,44.85 215.2,44.86 215.27,44.89 215.33,44.89 215.76,44.46 215.98,44.46 216.04,44.39 216.04,44.08 215.94,43.98 215.2,43.98 215.05,43.83 214.82,43.83 214.66,43.98 214.51,43.98 214.21,43.69 213.76,43.69 213.72,43.7 213.71,43.74 213.71,44.26 213.7,44.33 214.26,44.89
RING2 on BOTTOM (solid shape): 215.81,45.15 215.81,44.34 215.72,44.25 212.8,44.25 212.79,44.23 212.66,44.23 212.56,44.33 212.56,44.51 212.58,44.54 212.61,44.59 212.62,44.65 212.63,44.71 212.64,44.75 212.9,44.75 212.9,44.55 214.2,44.55 214.2,44.75 212.9,44.75 212.64,44.75 212.63,44.77 212.63,44.83 212.61,44.88 212.58,44.93 212.57,44.96 212.56,44.99 212.56,45.05 214.2,45.05 214.2,45.25 212.9,45.25 212.9,45.05 212.56,45.05 212.56,45.45 212.66,45.55 212.8,45.55 212.8,45.55 214.26,45.55 214.46,45.76 215.2,45.76
RING2 on IN3 (solid shape): 199.6,34.45 199.6,33.44 199.27,33.11 199.27,32.45 199.17,32.35 198.13,32.35 198,32.47 198,32.75 198.51,33.26 198.51,34.48 198.59,34.56 199.5,34.56
RING2 on IN3 (solid shape): 215.56,45.76 215.56,44.59 215.48,44.51 214.51,44.51 214.41,44.53 214.31,44.54 214.24,44.57 214.21,44.64 214.21,45.99 214.23,46.01 215.3,46.01
SLEEVE on TOP (solid shape): 214.96,43.47 215.35,43.47 215.38,43.44 215.38,43.3 215.39,43.25 215.4,43.2 215.4,43.12 215.64,42.89 215.9,42.89 216.02,42.77 216.02,42.31 215.92,42.21 214.07,42.21 213.68,42.61 213.68,43.11 213.75,43.18 214.43,43.18 214.72,43.48 214.96,43.48
SLEEVE on BOTTOM (solid shape): 216.01,43.83 216.01,42.91 215.81,42.7 215.02,42.7 214.85,42.54 214.59,42.54 214.37,42.76 212.84,42.76 212.79,42.82 212.79,43.01 212.83,43.05 214.2,43.05 214.2,43.25 212.82,43.25 212.79,43.28 212.79,43.52 212.82,43.55 214.2,43.55 214.2,43.75 212.83,43.75 212.79,43.79 212.79,43.97 212.85,44.03 215.81,44.03
SLEEVE on IN3 (solid shape): 215.5,43.88 215.5,42.94 215.25,42.68 214.29,42.68 213.98,42.99 213.98,43.8 214.18,44 215.38,44
TP_PWR_C on TOP (solid shape): 58.71,108.54 58.73,108.52 58.72,108.48 58.69,108.4 58.68,108.32 58.86,107.99 59.23,107.97 59.26,107.98 59.29,107.96 59.88,107.38 59.88,105.8 60.64,105.04 60.64,104 60.77,103.87 60.77,103.36 60.64,103.24 59.5,103.24 59.42,103.31 58.28,103.31 58.2,103.39 58.2,106.55 58.1,106.66 58.1,107.7 58.09,107.75 58.08,107.8 58.08,108.17 58.48,108.57 58.69,108.57
USBPWRD2 on BOTTOM (solid shape): 216.09,29.83 216.09,28.14 215.87,27.91 215.87,27.83 215.85,27.79 215.82,27.78 215.55,27.78 215.46,27.74 215.42,27.65 215.42,26.27 212.58,23.43 210.63,23.43 210.6,23.46 209.56,23.46 208.82,22.72 208.82,22.66 208.82,22.65 208.78,22.56 208.78,22.39 208.8,22.32 208.81,22.28 208.82,22.22 208.82,22.08 208.57,21.83 207.53,21.83 207.45,21.87 207.44,21.96 207.45,22.02 207.45,22.08 207.45,22.69 207.45,22.87 206.79,23.53 206.79,25.08 206.87,25.16 208.09,25.16 208.11,25.13 209.71,25.13 210.09,24.75 212.2,24.75 212.3,24.85 212.3,25.01 213.04,25.74 213.04,26.88 212.76,27.16 212.76,27.24 212.74,27.27 212.74,28.08 212.89,28.23 212.89,28.55 214.1,28.55 214.2,28.55 214.2,28.75 212.89,28.75 212.89,29.05 214.1,29.05 214.2,29.05 214.2,29.25 212.89,29.25 212.89,29.55 214.1,29.55 214.2,29.55 214.2,29.75 212.89,29.75 212.89,30.05 214.1,30.05 214.2,30.05 214.2,30.25 212.89,30.25 212.89,30.54 215.38,30.54
VA on TOP (solid shape): 131.02,34.92 131.02,34.78 130.87,34.64 130.87,33.26 131.23,32.9 131.23,32.33 130.96,32.07 129.16,32.07 128.97,32.26 128.97,33.48 129.02,33.57 129.11,33.58 129.19,33.55 129.27,33.54 129.52,33.64 129.63,33.9 129.62,33.96 129.6,34.03 129.6,34.94 129.83,35.17 130.77,35.17
VA on TOP (solid shape): outline of 222 points within 8.82,113.02 42.23,122.77
VA on BOTTOM (solid shape): 42,119.14 42,116.57 41.87,116.45 41.24,116.45 40.19,117.49 40.19,119.32 40.22,119.34 41.79,119.34
VA on BOTTOM (solid shape): 12.76,118.48 14.41,116.83 22.16,116.83 22.16,115.81 22.03,115.68 9.86,115.68 9.66,115.88 9.66,117.56 10.14,118.04 11.3,118.04 11.31,117.98 11.32,117.93 11.34,117.87 11.37,117.83 11.4,117.78 11.44,117.74 11.49,117.71 11.54,117.68 11.59,117.67 11.64,117.66 11.7,117.65 11.76,117.66 11.81,117.67 11.86,117.7 11.91,117.73 11.95,117.76 11.99,117.8 12.02,117.85 12.04,117.9 12.06,117.95 12.07,118.01 12.07,118.06 12.06,118.12 12.04,118.17 12.02,118.22 11.99,118.27 11.95,118.31 11.91,118.35 11.86,118.38 11.81,118.4 11.76,118.41 11.7,118.42 11.64,118.42 11.59,118.41 11.54,118.39 11.49,118.36 11.44,118.33 11.4,118.29 11.37,118.25 11.34,118.2 11.32,118.15 11.31,118.09 11.3,118.04 10.14,118.04 10.28,118.17 10.28,118.23 10.31,118.25 10.36,118.3 10.41,118.36 10.45,118.43 10.48,118.49 10.51,118.57 10.52,118.64 10.53,118.71 10.53,118.79 10.52,118.86 10.51,118.93 10.5,118.96 10.52,119.03 10.57,119.16 10.61,119.3 10.63,119.37 12.76,119.37
VA on IN1 (solid shape): outline of 405 points within 9.62,115.05 42.23,122.67
VA on IN2 (solid shape): 125.79,42.4 125.79,40.98 125.69,40.88 124.57,40.88 124.47,40.98 124.47,42.3 124.67,42.51 125.69,42.51
VA on IN2 (solid shape): outline of 493 points within 9.65,115.05 43.75,122.67
VA on SVCC (solid shape): 43.5,123.07 43.5,117.69 40.09,114.29 39.85,114.29 39.4,114.74 39.06,114.97 38.67,115.05 26.22,115.05 25.83,114.97 25.5,114.74 23.52,112.76 22.33,112.76 21.11,113.98 20.78,114.21 20.38,114.29 19.11,114.29 18.72,114.21 18.39,113.98 16.62,112.22 16.4,111.89 16.32,111.49 16.32,104.67 14.5,102.86 13.35,102.86 12.92,103.29 12.72,104.02 12.22,104.59 12.22,105.17 12.23,105.19 12.53,105.19 12.93,105.27 13.26,105.5 15.15,107.39 15.38,107.72 15.45,108.11 15.45,110.27 15.38,110.67 15.15,111 13.21,112.94 12.88,113.17 12.48,113.24 9.97,113.24 9.96,113.53 9.91,113.8 10.33,114.01 10.51,114.45 10.32,114.91 9.86,115.1 9.57,115.1 9.57,118.08 9.86,118.08 10.33,118.27 10.53,118.75 10.35,119.21 9.92,119.42 9.93,119.48 10.33,119.88 13.06,119.88 13.48,119.46 13.48,119.4 14.07,117.97 15.5,117.38 32.7,117.38 34.13,117.97 34.72,119.4 34.72,123.06 35.04,123.38 43.19,123.38
VA on IN3 (solid shape): 125.79,41.53 125.82,41.53 125.98,41.36 126.17,41.31 126.31,41.34 126.42,41.41 126.49,41.43 126.56,41.41 126.78,41.31 127.01,41.37 130.95,37.43 130.95,33.87 130.8,33.72 129.83,33.72 129.75,33.79 129.75,35.41 125.18,39.98 125.18,40.14 124.34,40.98 124.33,41.01 124.33,41.03 124.34,41.08 124.34,41.13 124.32,41.25 124.25,41.37 124.24,41.39 124.24,41.49 124.29,41.53
VA on IN3 (solid shape): outline of 400 points within 9.61,115.05 42.23,122.67
VA2 on TOP (solid shape): 44.66,120.71 44.7,120.7 44.72,120.66 44.72,117.33 44.36,116.98 42.66,116.98 42.48,117.16 42.48,120.46 42.73,120.71
N17047007 on TOP (solid shape): 51.52,118.93 51.52,114.67 51.38,114.53 51.21,114.53 51.19,114.53 51.04,114.64 50.89,114.67 50.75,114.64 50.64,114.58 50.6,114.56 50.57,114.58 50.27,114.88 50.24,114.93 50.21,114.97 50.18,115.04 50.21,115.1 50.28,115.22 50.3,115.35 50.19,115.62 49.92,115.73 49.78,115.71 49.66,115.63 49.59,115.6 49.53,115.62 49.51,115.63 49.34,115.81 45.91,115.81 45.25,116.47 45.25,120.33 45.26,120.37 45.3,120.38 46.13,120.38 46.16,120.4 46.18,120.41 50.05,120.41
N17047087 on TOP (solid shape): 118.58,27.01 118.58,25.23 118.48,25.13 113.11,25.13 112.95,25.28 112.95,25.78 114.49,27.32 118.27,27.32
N17047087 on BOTTOM (solid shape): 117.58,30.92 117.58,27.42 118.68,26.32 118.68,25.39 118.43,25.13 113.22,25.13 112.96,25.39 111.97,25.39 111.92,25.44 111.92,28.59 112.15,28.82 112.81,28.82 113.09,29.11 113.09,31.11 113.32,31.34 117.16,31.34
N18867651 on TOP (solid shape): 153.7,26.15 153.74,26.13 153.75,26.1 153.75,25.38 153.95,25.38 153.95,26.08 153.96,26.09 154.14,26.09 154.15,26.07 154.15,25.35 154.22,25.28 154.22,25.08 154.39,24.91 154.39,24.59 154.36,24.58 154.16,24.44 154.09,24.22 154.16,23.99 154.36,23.85 154.39,23.84 154.39,23.45 154.38,23.42 154.34,23.4 154.27,23.4 154.11,23.33 154.04,23.17 154.04,22.9 153.91,22.77 151.83,22.77 151.8,22.8 151.8,23.4 151.95,23.56 152.1,23.56 152.45,23.91 152.46,23.91 152.63,24.04 152.69,24.24 152.59,24.49 152.33,24.6 152.23,24.6 151.95,24.88 151.95,26.15 152.28,26.15
N18867812 on TOP (solid shape): 20.43,31.57 20.51,31.36 20.68,31.23 20.71,31.21 20.71,30.06 20.86,29.91 20.9,29.87 20.94,29.83 21.07,29.7 21.4,29.7 21.53,29.57 21.53,28.93 21.68,28.79 21.68,28.71 21.68,28.57 21.66,28.53 21.63,28.52 20.91,28.52 20.91,28.32 21.63,28.32 21.66,28.3 21.68,28.27 21.68,28.17 21.66,28.13 21.63,28.12 20.91,28.12 20.91,28.1 20.88,28.07 20.09,28.07 19.95,28.21 18.96,28.21 18.86,28.31 18.83,28.38 18.86,28.45 18.88,28.49 18.89,28.54 18.89,29.91 18.86,30 18.77,30.03 18.71,30.03 18.71,31.16 18.71,31.16 18.71,31.56 18.76,31.61 20.43,31.61
N18922914 on TOP (solid shape): 100.94,110.18 100.97,110.15 101,110.12 101.1,110.02 101.1,108.88 100.13,107.9 100.1,107.89 100.06,107.9 99.99,107.95 99.91,107.96 99.61,107.96 99.49,107.93 99.4,107.84 99.4,107.82 99.37,107.81 97.52,107.81 97.24,108.09 97.24,108.47 97.39,108.62 98.41,108.62 98.49,108.7 98.49,108.72 98.54,108.81 98.65,108.8 98.75,108.74 98.87,108.72 99.22,109.08 98.87,109.44 98.83,109.43 98.77,109.46 98.79,109.52 98.8,109.54 98.86,109.61 98.9,109.68 98.92,109.71 98.94,109.71 99.88,109.71 99.96,109.79 99.98,109.79 100.12,109.85 100.18,110 100.19,110.02 100.39,110.22 100.9,110.22
N22415444 on TOP (solid shape): 111.14,40.49 111.14,40.48 111.54,40.08 111.54,40.08 111.76,39.86 112.34,39.86 112.49,39.71 112.49,33.68 112.2,33.39 112.2,33.39 112,33.44 111.8,33.39 110.5,33.39 110.3,33.18 107.02,33.18 106.72,33.49 106.53,33.49 106.08,33.94 106.13,33.99 106.13,35.09 106.24,35.19 109.46,35.19 109.57,35.3 109.82,35.3 109.91,35.33 109.94,35.42 109.94,35.67 110.07,35.8 110.07,35.87 110.16,35.96 110.16,40.22 110.49,40.54 111.09,40.54
N22415444 on BOTTOM (solid shape): outline of 91 points within 105.54,33.97 112.59,41.92
N24507636 on TOP (solid shape): 170.75,26.58 170.75,22.9 170.7,22.85 167.88,22.85 167.41,23.32 167.41,24.3 168.59,24.3 168.59,24.24 168.6,24.19 168.61,24.14 168.64,24.09 168.67,24.05 168.7,24.01 168.75,23.97 168.79,23.95 168.84,23.93 168.89,23.92 168.95,23.91 169,23.92 169.05,23.93 169.1,23.95 169.15,23.97 169.19,24.01 169.23,24.05 169.26,24.09 169.28,24.14 169.29,24.19 169.3,24.24 169.3,24.3 169.29,24.35 169.28,24.4 169.26,24.45 169.23,24.49 169.19,24.53 169.15,24.56 169.1,24.59 169.05,24.61 169,24.62 168.95,24.63 168.89,24.62 168.84,24.61 168.79,24.59 168.75,24.56 168.7,24.53 168.67,24.49 168.64,24.45 168.61,24.4 168.6,24.35 168.59,24.3 167.41,24.3 167.41,24.46 167.55,24.6 168.16,24.6 168.46,24.9 168.8,24.9 169.09,24.9 169.35,25.17 169.35,26.53 169.45,26.63 170.7,26.63
N24507636 on BOTTOM (solid shape): 167.61,24.37 167.69,24.34 167.71,24.26 167.71,24.25 167.71,23.91 167.75,23.82 167.84,23.78 168.22,23.78 168.3,23.81 168.34,23.87 168.44,23.97 168.73,23.97 168.86,23.87 169.01,23.83 169.02,23.83 169.16,23.86 169.28,23.94 169.51,23.94 169.73,23.72 169.73,22.47 169.61,22.34 168.97,22.34 168.72,22.59 167.7,22.59 167.57,22.47 167.57,21.96 167.45,21.83 166.3,21.83 166.05,22.08 166.05,23.48 166.1,23.53 166.12,23.53 166.34,23.65 166.43,23.89 166.41,24.01 166.34,24.12 166.33,24.14 166.33,24.2 166.31,24.31 166.4,24.37
N24742093 on BOTTOM (solid shape): 69.52,107.17 69.56,107.16 69.57,107.12 69.57,106.69 69.61,106.6 69.7,106.56 70.19,106.56 70.22,106.54 70.22,101.08 70.66,100.63 71.88,100.63 71.94,100.57 71.94,99.05 71.93,99.01 71.89,99 71.42,98.68 71.53,98.13 71.61,98.05 71.77,97.94 71.97,97.9 72.4,97.9 72.44,97.89 72.45,97.85 72.45,95.62 72.32,95.49 70.67,95.49 70.56,95.61 70.56,97.24 70.55,97.25 70.55,97.27 70.47,97.35 70.46,97.35 69.66,98.16 69.66,100.37 69.33,100.7 69.33,100.7 68.64,100.7 68.39,100.95 68.39,105.27 68.77,105.65 68.77,107.05 68.9,107.17
N24742107 on TOP (solid shape): 22.03,100.39 22.03,95.99 21.96,95.92 21.96,95.04 21.93,95.01 21.92,94.98 21.9,94.95 21.87,94.94 21.84,94.94 21.84,94.27 21.83,94.23 21.79,94.22 21.69,94.22 21.65,94.23 21.64,94.27 21.64,94.94 21.44,94.94 21.44,94.27 21.43,94.23 21.39,94.22 21.02,94.22 20.76,94.47 20.76,98.54 19.98,99.33 19.98,100.52 20.94,101.48
N28087213 on TOP (solid shape): 38.16,112.51 38.16,111.87 38.03,111.75 27.8,111.75 27.32,111.26 25.36,111.26 25.23,111.39 25.23,112.51 25.49,112.76 37.91,112.76
N28087213 on BOTTOM (solid shape): 25.87,112.61 25.87,111.64 24.74,110.79 23.44,110.14 20.81,109.08 18.86,109.08 18.48,109.46 18.48,110.73 19.75,112 20.03,112 20.74,111.29 21.42,110.93 21.8,110.93 23.36,111.71 23.96,112.13 24.62,112.79 25.69,112.79
N30319022 on TOP (solid shape): 140.54,77.94 140.55,77.93 140.56,77.52 140.58,77.45 140.62,77.41 140.64,77.4 140.65,77.38 140.65,77.2 140.93,76.92 142.12,76.92 142.71,76.34 142.71,74.74 142.4,74.43 137.45,74.43 137.15,74.74 137.15,76.44 137.7,77 138.64,77 138.72,77.08 138.72,77.68 139,77.96 140.52,77.96
N30319022 on BOTTOM (solid shape): 137.26,78.68 137.3,78.66 137.31,78.62 137.31,78.57 137.3,78.56 137.22,78.43 137.2,78.29 137.31,78.02 137.58,77.91 137.72,77.94 137.85,78.02 138.08,78.25 138.08,78.39 138.14,78.48 138.25,78.46 138.58,78.13 142.57,78.13 142.66,78.04 142.66,77.15 142.68,77.13 142.68,74.74 142.39,74.45 134.75,74.45 133.32,75.87 133.29,75.95 133.33,76.02 133.43,76.15 133.46,76.31 133.35,76.58 133.05,76.71 133.03,76.75 133.03,78.4 133.31,78.68
N30442035 on TOP (solid shape): 21.66,26.68 21.66,26.52 20.91,26.52 20.91,26.32 21.63,26.32 21.66,26.29 21.66,25.82 21.07,25.23 21.07,22.95 20.81,22.69 20.27,22.69 20.23,22.71 20.18,22.72 20.13,22.72 20.07,22.72 20.02,22.71 19.99,22.69 18.65,22.69 18.46,22.89 18.46,23.63 19.8,23.63 19.8,23.58 19.81,23.52 19.83,23.47 19.86,23.42 19.89,23.38 19.93,23.34 19.98,23.31 20.03,23.28 20.08,23.26 20.14,23.25 20.19,23.25 20.25,23.26 20.3,23.27 20.35,23.29 20.4,23.32 20.44,23.36 20.48,23.4 20.51,23.45 20.54,23.5 20.55,23.55 20.56,23.61 20.56,23.66 20.55,23.72 20.54,23.77 20.51,23.82 20.48,23.87 20.44,23.91 20.4,23.94 20.35,23.97 20.3,24 20.25,24.01 20.19,24.02 20.14,24.01 20.08,24 20.03,23.99 19.98,23.96 19.93,23.93 19.89,23.89 19.86,23.84 19.83,23.8 19.81,23.74 19.8,23.69 19.8,23.63 18.46,23.63 18.46,24.14 18.46,24.16 18.45,24.19 18.43,24.22 18.41,24.24 18.38,24.26 18.35,24.27 18.22,24.27 18.22,25.72 18.87,26.37 20.48,26.37 20.83,26.71 21.63,26.71
N31069510 on TOP (solid shape): 155.75,25.38 155.95,25.38 155.95,26.09 157.09,26.09 157.8,25.39 157.8,24.75 158.18,24.37 159.68,24.37 159.78,24.27 159.78,23 159.73,22.95 156.17,22.95 156.02,23.1 156.02,23.48 155.76,23.74 155.76,23.79 155.84,23.86 156.05,23.99 156.13,24.23 156.04,24.48 155.81,24.61 155.76,24.65 155.76,24.88 155.55,25.09 155.55,26.06 155.58,26.09 155.75,26.09
N31297491 on TOP (solid shape): 26.55,24.01 26.55,23.66 27.03,23.18 27.13,23.18 27.37,23.1 27.61,23.18 28.21,23.18 28.42,22.97 29.73,22.97 29.93,22.77 29.93,21.83 29.88,21.78 28.52,21.78 28.16,22.14 28.13,22.14 28.04,22.22 24.12,22.22 24.11,22.23 23.44,22.23 23.23,22.44 23.23,22.92 23,23.15 23,23.45 23.08,23.53 24.3,23.53 24.5,23.33 25.54,23.33 25.72,23.51 25.72,23.94 25.89,24.12 26.45,24.12
N31297491 on BOTTOM (solid shape): 26.1,23.76 26.1,22.8 26.06,22.76 26.05,22.76 24.02,22.76 24.01,22.77 23.66,22.41 23.46,22.41 23.25,22.62 23.25,23.68 23.44,23.87 23.85,23.87 23.94,23.96 25.89,23.96
N31353058 on TOP (solid shape): outline of 126 points within 31.43,27.04 37.4,31.86
N31375926 on BOTTOM (solid shape): 110.42,45.58 110.42,44.31 110.3,44.18 110.3,43.8 110.04,43.8 109.92,43.93 108.77,43.93 108.77,44.31 109.41,44.31 109.92,44.82 109.92,45.5 110.07,45.66 110.35,45.66
N36953746 on TOP (solid shape): 52,21.7 52,21.42 51.88,21.3 51.88,20.94 52.39,20.43 52.72,20.43 52.89,20.26 52.89,18.46 52.84,18.4 52.36,18.4 52.03,18.73 52.03,18.96 52.06,18.99 52.06,19.67 51.98,19.75 51.85,20.03 51.56,20.15 51.51,20.2 50.92,20.2 50.82,20.31 50.82,21.1 51.04,21.32 51.63,21.91 51.8,21.91
N38517597 on TOP (solid shape): 15.79,13.55 16.74,13.55 16.84,13.45 16.84,12.93 17.21,12.56 17.21,11.92 17.08,11.8 16.7,11.8 16.48,12.01 15.34,12.01 15.05,12.31 15.05,13.56 15.17,13.69 15.66,13.69
N38517632 on TOP (solid shape): 21.6,17.46 21.6,17.33 21.5,17.24 21.5,15.74 21.42,15.66 20.25,15.66 20.18,15.73 20.18,17.54 21.52,17.54
N38756671 on TOP (solid shape): 200.34,15.61 200.34,14.34 199.35,13.35 199.35,12.28 198.84,11.77 198.84,10.6 198.74,10.5 197.88,10.5 197.62,10.76 197.62,12.38 198.13,12.89 198.13,13.91 199.96,15.73 200.21,15.73
N39687060 on TOP (solid shape): 66.51,118.47 66.51,117.1 66.64,116.97 66.64,115.48 67.07,115.05 67.07,114.77 66.99,114.69 66.69,114.69 65.82,115.56 65.82,116.57 65.95,116.7 65.95,118.33 65.9,118.38 65.88,118.49 65.97,118.55 66.43,118.55
N39687064 on TOP (solid shape): 61.05,124.7 61.05,121.5 61.53,121.02 61.66,121.02 61.68,121 62.47,121 62.48,121.03 62.52,121.07 62.6,121.07 62.72,121.27 63.82,121.27 63.94,121.14 63.94,118.73 63.82,118.6 62.93,118.6 62.8,118.73 62.8,119.37 62.57,119.59 62.46,119.59 62.46,119.6 61.68,119.6 61.68,119.59 57.34,119.59 57.13,119.8 62.46,119.8 62.46,120 61.68,120 61.68,119.8 57.13,119.8 56.81,120.13 56.81,120.2 62.46,120.2 62.46,120.4 61.68,120.4 61.68,120.2 56.81,120.2 56.81,120.6 62.46,120.6 62.46,120.8 61.68,120.8 61.68,120.6 56.81,120.6 56.81,124.29 57.29,124.78 60.97,124.78
N39687102 on TOP (solid shape): 52.72,124.78 52.72,124.21 52.72,124.07 52.75,124.03 52.76,124.02 52.9,123.87 53.1,123.81 53.2,123.82 53.29,123.86 54.75,123.86 55.61,123 55.61,119.32 54.7,118.4 52.23,118.4 51.65,118.98 51.65,118.99 50.1,120.53 50.1,120.53 49.34,121.3 49.34,121.59 49.35,121.61 49.36,121.62 49.39,121.66 49.41,121.72 49.41,122.1 49.4,122.13 49.38,122.17 49.36,122.23 49.39,122.29 49.44,122.39 49.46,122.5 49.5,122.56 49.57,122.59 50.48,122.59 50.66,122.77 50.99,122.77 50.99,123.1 50.99,123.1 50.99,124.12 51.14,124.27 51.78,124.27 51.8,124.24 51.98,124.42 51.98,124.7 52.16,124.88 52.61,124.88
N39687102 on BOTTOM (solid shape): 57.08,123 57.08,120.15 55.54,118.6 47.81,118.6 47.18,119.24 47.18,120.38 47.43,120.64 48.67,120.64 49.05,121.02 49.05,122.04 49.18,122.17 49.19,122.17 49.36,122.26 49.46,122.43 49.46,122.45 50.43,123.42 56.67,123.42
N39687482 on TOP (solid shape): 70.8,120.64 70.8,119.87 70.67,119.75 69.53,119.75 69.02,120.26 69.02,120.51 68.54,120.99 68.54,121.8 68.77,122.03 69.4,122.03
N39687482 on TOP (solid shape): 66.13,123.38 66.13,123.15 65.92,122.95 65.75,122.95 65.21,122.41 65.21,121.63 65.09,121.5 64.63,121.5 64.59,121.51 64.58,121.55 64.58,122.29 64.55,122.31 64.55,122.49 64.91,122.85 64.91,123.4 64.98,123.48 66.03,123.48
N39687482 on BOTTOM (solid shape): 66.52,125.23 66.61,125.2 66.71,125.18 66.8,125.19 66.89,125.23 66.9,125.23 67.07,125.23 67.19,125.11 67.19,124.22 65.92,122.95 65.06,122.95 64.92,123.09 64.92,123.77 65.14,123.99 65.85,123.99 65.97,124.12 65.97,124.98 66.2,125.2 66.27,125.23
N39687482 on IN2 (solid shape): 67.27,123.89 67.38,123.68 67.61,123.59 67.63,123.59 67.78,123.43 68.26,123.43 69.66,122.03 69.66,120.76 69.4,120.51 68.9,120.51 68.52,120.89 68.52,121.1 67.71,121.91 66.97,121.91 66.88,121.96 66.88,122.06 66.93,122.16 66.94,122.26 66.84,122.51 66.58,122.62 66.38,122.55 66.25,122.37 66.17,122.31 66.08,122.33 66.02,122.39 65.36,122.39 64.89,122.87 65.04,123.02 65.04,123.44 64.81,123.66 65.09,123.94 67.27,123.94
N47271970 on BOTTOM (solid shape): 96.71,88.76 96.71,88.51 95.97,87.77 95.97,87.16 95.92,87.11 95.62,87.11 94.35,88.38 93.38,88.38 93.28,88.48 93.28,88.89 96.58,88.89

Small or netless copper shapes (teardrops, artwork), in the pictures only: 41 on TOP, 22 on BOTTOM, 6 on IN1, 49 on IN2, 2 on IN3

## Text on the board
Ref Des/Silkscreen Bottom: DA0ZAWMB8B0  REV:B
User.Comments: 16x35 | 26x33 | 33x37
Ref Des/Silkscreen Top: MODEL:ZAW | DA0ZAWMB8C0  REV:C
User.6: 145 | 219.8 | 128
User.8: 145 | 219.8 | 128
User.12: VCCPRIM_1P8 | +VCCLDOSRAM_1P24 | VCCPRIM_3P3 | GND | +3V_S5 | VA | +1.2VSUS | +3V | +5VPCU | +1.8V_S5 | +VCC_CORE | +1.05V_DEEP_SUS | +VGPU_CORE | +VCCGT | +VCCSA | +5V | +5V_S5 | ADOGND
User.36: GND | ADOGND
User.37: ADOGND | GND
User.45: FIGURE | TYPE | Oblong | Rectangle | Circle | SIZE | 43.0x20.0 | 59.0x20.0 | 59.0x28.0 | 63.0x31.0 | 71.0x31.0 | 75.0x39.0 | 91.0x28.0 | 102.0x31.0 | 118.0x20.0 | 252.0x232.0 | 157.0x157.0 | 8.0 | 10.0 | 12.0 | 14.0 | 16.0 | 22.0 | 28.0 | 35.0 | 102.0 | 118.0 | 126.0 | 150.0 | 220.0 | 26.0 | 41.0 | 43.0 | 47.0 | 63.0 | 67.0 | 75.0 | 98.0 | DRILL CHART: TOP to BOTTOM | ALL UNITS ARE IN MILS | PLATED | NON-PLATED | ROTATION | 90.000 | 0.000 | - | QTY | 2 | 6 | 4 | 1 | 33 | 6014 | 19 | 5 | 135 | 48 | 10 | 18 | 8 | 3 | 6299 | TOTAL HOLES:
